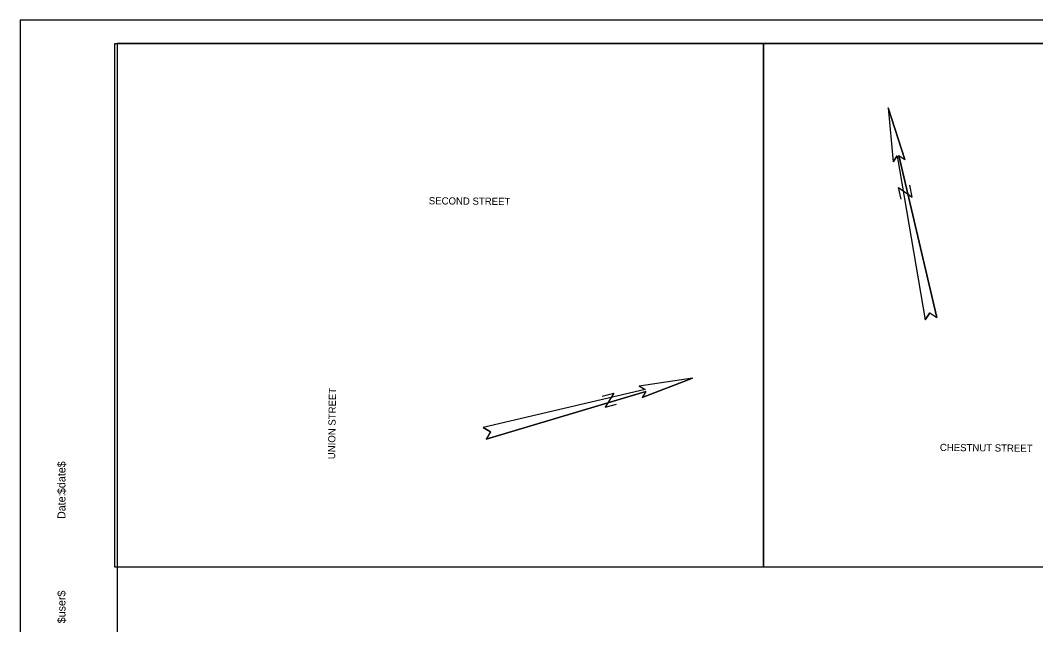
# Model space of a CAD drawing. Extents: x 0 to 850, y 0 to 550.
# Drawn here: x -0.1 to 424.7, y 297.1 to 549.9 of the extents above; entities that cross this region are included whole.
import ezdxf

# ---------------------------------------------------------------- set-up
doc = ezdxf.new("R2010")
doc.units = 0
for name, color, linetype in [('BORDER', 7, 'Continuous'), ('D_Roadway_Centerline_Text', 7, 'Continuous'), ('Default', 7, 'Continuous'), ('H_V CONTROLS', 7, 'Continuous'), ('PLOT BOUNDARY', 7, 'Continuous')]:
    doc.layers.add(name, color=color, linetype=linetype)

msp = doc.modelspace()

# ---------------------------------------------------------------- linework, layer by layer
at = {"layer": 'BORDER'}
for p, q in [((840.33, 540.24), (40.33, 540.24)), ((40.33, 540.24), (40.33, 15.24))]:
    msp.add_line(p, q, dxfattribs=at)
at = {"layer": 'Default'}
for points in [[(39.35, 540.24), (310.76, 540.24), (310.76, 321.19), (39.35, 321.19)], [(40.33, 15.24), (790.33, 15.24), (790.33, 540.26), (40.33, 540.26)], [(310.76, 540.24), (513.56, 540.24), (513.56, 321.19), (310.76, 321.19)]]:
    msp.add_lwpolyline(points, close=True, dxfattribs=at)
at = {"layer": 'H_V CONTROLS'}
for p, q in [((363.04, 513.29), (365.05, 490.74)), ((363.04, 513.29), (369.95, 491.74)), ((366.71, 493.24), (365.05, 490.74)), ((366.71, 493.24), (378.44, 424.59)), ((367.46, 493.39), (369.95, 491.74)), ((367.46, 493.39), (383.34, 425.58)), ((380.4, 427.53), (378.44, 424.59)), ((380.4, 427.53), (383.34, 425.58)), ((281.14, 400.3), (258.76, 396.94)), ((281.14, 400.3), (260.04, 392.11)), ((261.34, 395.44), (193.52, 379.61)), ((261.34, 395.44), (258.76, 396.94)), ((261.54, 394.69), (194.8, 374.77)), ((261.54, 394.69), (260.04, 392.11)), ((196.58, 377.83), (193.52, 379.61)), ((196.58, 377.83), (194.8, 374.77))]:
    msp.add_line(p, q, dxfattribs=at)
for points in [[(380.4, 427.53), (383.34, 425.58), (367.46, 493.39), (369.95, 491.74), (363.04, 513.29), (365.05, 490.74), (366.71, 493.24), (378.44, 424.59), (380.4, 427.53)], [(372.99, 476.03), (372, 480.93)], [(368.36, 475.09), (367.37, 479.99)], [(367.37, 479.99), (372.99, 476.03)], [(196.58, 377.83), (194.8, 374.77), (261.54, 394.69), (260.04, 392.11), (281.14, 400.3), (258.76, 396.94), (261.34, 395.44), (193.52, 379.61), (196.58, 377.83)], [(243.33, 392.7), (248.16, 393.98)], [(248.16, 393.98), (244.54, 388.13)], [(244.54, 388.13), (249.37, 389.41)]]:
    msp.add_lwpolyline(points, dxfattribs=at)
at = {"layer": 'PLOT BOUNDARY'}
msp.add_lwpolyline([(-0.13, -0.05), (849.87, -0.05), (849.87, 549.95), (-0.13, 549.95)], close=True, dxfattribs=at)

# ---------------------------------------------------------------- texts
at = {"layer": 'BORDER'}
for s, p in [('$date$', (18.76, 351.77)), ('Date:', (18.76, 341.33)), ('$user$', (18.76, 297.7))]:
    msp.add_text(s, height=3.348, rotation=90, dxfattribs=at).set_placement(p)
at = {"layer": 'D_Roadway_Centerline_Text'}
for s, rotation, p in [('SECOND STREET', 359.4945, (170.78, 472.97)), ('UNION STREET', 89.2421, (131.59, 366.33)), ('CHESTNUT STREET', 359.4115, (384.61, 369.8))]:
    msp.add_text(s, height=3, rotation=rotation, dxfattribs=at).set_placement(p)

doc.saveas('drawing.dxf')
